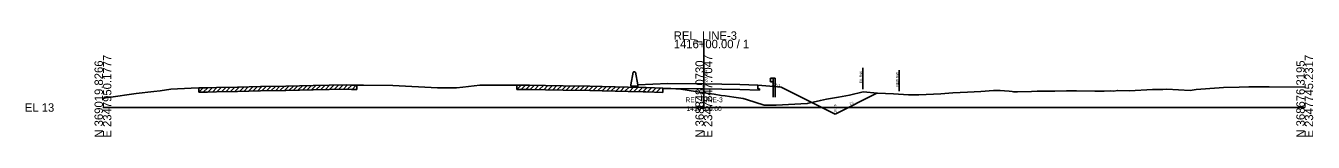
# Model space of a CAD drawing. Extents: x -26 to 2346329, y -10 to 370015.
# Drawn here: x 1974.3 to 2402.8, y 8490.3 to 8525.3 of the extents above; entities that cross this region are included whole.
import ezdxf

# ---------------------------------------------------------------- set-up
doc = ezdxf.new("R2010")
doc.units = 0
for name, color, linetype in [('RD_HC_Cl', 7, 'Continuous'), ('RD_HC_CL_Rel', 7, 'Continuous'), ('RD_HC_Data', 7, 'Continuous'), ('RD_HC_Data_Tic', 7, 'Continuous'), ('RD_HC_Data_Tic_Rel', 7, 'Continuous'), ('RD_HC_TX_Rel_Sta50', 7, 'Continuous'), ('RD_HC_TX_Sta50', 7, 'Continuous'), ('RD_PD_PatLn_526', 7, 'Continuous'), ('RD_PD_PatLn_LINE-A', 7, 'Continuous'), ('RD_PD_PatLn_LINE-B', 7, 'Continuous'), ('RD_PD_PatLn_REL_L-2118', 7, 'Continuous'), ('RD_PD_PatLn_REL_L-2523', 7, 'Continuous'), ('RD_PD_PatLn_Rel_LINE-3', 7, 'Continuous'), ('RD_PD_SuperShp2', 7, 'Continuous'), ('RD_TX_RoadID', 7, 'Continuous'), ('RD_TX_StaOff', 7, 'Continuous'), ('RD_XS_Pave', 7, 'Continuous')]:
    doc.layers.add(name, color=color, linetype=linetype)

msp = doc.modelspace()

# ---------------------------------------------------------------- linework, layer by layer
at = {"layer": 'RD_HC_Cl'}
for p, q in [((2200, 8500), (2200, 8522.45)), ((2000, 8500), (2200, 8500)), ((2200, 8500), (2400, 8500))]:
    msp.add_line(p, q, dxfattribs=at)
at = {"layer": 'RD_HC_Data'}
msp.add_lwpolyline([(2000, 8503.04), (2001.19, 8503.27), (2001.98, 8503.39), (2002.63, 8503.46), (2010.33, 8504.54), (2011.08, 8504.63), (2016.93, 8505.3), (2019.08, 8505.58), (2022.57, 8506.04), (2029.35, 8506.37), (2031.91, 8506.49), (2034.8, 8506.55), (2037.81, 8506.59), (2044.83, 8506.75), (2052.47, 8506.92), (2060.86, 8507.09), (2069.97, 8507.26), (2075.28, 8507.37), (2081.14, 8507.48), (2082.75, 8507.45), (2084.45, 8507.42), (2086.69, 8507.44), (2096.52, 8507.26), (2111.37, 8506.52), (2112.69, 8506.51), (2117.68, 8506.53), (2119.79, 8506.74), (2125.39, 8507.37), (2126.89, 8507.39), (2135.27, 8507.43), (2137.71, 8507.39), (2139.85, 8507.42), (2142, 8507.45), (2147.35, 8507.34), (2153.19, 8507.22), (2162.07, 8507.07), (2166.13, 8507), (2174.86, 8506.8), (2179.77, 8506.68), (2180.66, 8506.65), (2186.39, 8506.44), (2189.03, 8506.29), (2192.38, 8506.08), (2200, 8504.91), (2203.39, 8504.38), (2205.77, 8504.03), (2207.07, 8503.88), (2210, 8503.42), (2213.08, 8503.02), (2214.24, 8502.7), (2220.04, 8500.77), (2224.08, 8500.74), (2234.42, 8501.32), (2238.78, 8502.33), (2240.87, 8502.73), (2244.81, 8503.44), (2248.51, 8504.11), (2253.07, 8505.17), (2257.8, 8504.72), (2263.08, 8504.55), (2268.09, 8504.15), (2271.61, 8504.2), (2278.87, 8504.5), (2282.83, 8504.9), (2287.77, 8505.1), (2292.19, 8505.3), (2296.38, 8505.67), (2298.66, 8505.69), (2300.05, 8505.56), (2301.65, 8505.41), (2302.61, 8505.28), (2303.04, 8505.22), (2303.4, 8505.23), (2304.38, 8505.22), (2309.11, 8505.35), (2311, 8505.41), (2313.93, 8505.41), (2316.79, 8505.38), (2320.68, 8505.57), (2324, 8505.51), (2330.1, 8505.41), (2333.24, 8505.41), (2335.27, 8505.48), (2336.44, 8505.41), (2337.64, 8505.66), (2341.71, 8505.57), (2349.37, 8505.95), (2352.76, 8506), (2354.09, 8506.03), (2361.82, 8505.67), (2363.91, 8505.93), (2371.51, 8506.56), (2373, 8506.59), (2378.21, 8506.73), (2381.4, 8506.82), (2384.57, 8506.9), (2385.38, 8506.88), (2388.17, 8506.86), (2400, 8506.74)], dxfattribs=at)
at = {"layer": 'RD_HC_Data_Tic_Rel'}
for p, q in [((2178, 8507.53), (2178, 8506.73)), ((2225.75, 8506.74), (2243.7, 8497.76)), ((2243.7, 8497.76), (2257.63, 8504.72))]:
    msp.add_line(p, q, dxfattribs=at)
at = {"layer": 'RD_HC_TX_Rel_Sta50'}
for p, q in [((2188, 8507.93), (2200, 8507.84)), ((2200, 8507.84), (2212, 8507.6))]:
    msp.add_line(p, q, dxfattribs=at)
at = {"layer": 'RD_HC_TX_Sta50'}
for p, q in [((2031.91, 8505.05), (2033.38, 8506.52)), ((2031.91, 8505.05), (2031.91, 8506.49)), ((2033.41, 8505.08), (2034.88, 8506.55)), ((2034.91, 8505.11), (2036.37, 8506.57)), ((2036.41, 8505.13), (2037.87, 8506.59)), ((2037.91, 8505.16), (2039.38, 8506.63)), ((2039.41, 8505.19), (2040.88, 8506.66)), ((2040.91, 8505.23), (2042.38, 8506.7)), ((2042.41, 8505.26), (2043.88, 8506.73)), ((2043.91, 8505.29), (2045.38, 8506.76)), ((2045.41, 8505.33), (2046.88, 8506.8)), ((2046.91, 8505.36), (2048.38, 8506.83)), ((2048.41, 8505.4), (2049.88, 8506.87)), ((2049.91, 8505.43), (2051.38, 8506.9)), ((2051.41, 8505.46), (2052.88, 8506.93)), ((2052.91, 8505.5), (2054.38, 8506.96)), ((2054.41, 8505.52), (2055.88, 8506.99)), ((2055.91, 8505.55), (2057.38, 8507.02)), ((2057.41, 8505.58), (2058.88, 8507.05)), ((2058.91, 8505.61), (2060.38, 8507.08)), ((2060.41, 8505.64), (2061.88, 8507.1)), ((2061.91, 8505.67), (2063.38, 8507.13)), ((2063.41, 8505.7), (2064.88, 8507.16)), ((2064.91, 8505.73), (2066.38, 8507.19)), ((2066.41, 8505.75), (2067.88, 8507.22)), ((2067.91, 8505.78), (2069.38, 8507.25)), ((2069.41, 8505.81), (2070.88, 8507.28)), ((2070.91, 8505.84), (2072.38, 8507.31)), ((2072.41, 8505.87), (2073.88, 8507.34)), ((2073.91, 8505.9), (2075.38, 8507.37)), ((2075.41, 8505.93), (2076.88, 8507.4)), ((2076.91, 8505.96), (2078.38, 8507.43)), ((2078.41, 8505.99), (2079.88, 8507.46)), ((2079.91, 8506.02), (2081.37, 8507.48)), ((2081.41, 8506.04), (2082.82, 8507.45)), ((2082.91, 8506.01), (2084.32, 8507.42)), ((2084.45, 8507.42), (2084.45, 8505.98)), ((2137.71, 8505.95), (2139.18, 8507.41)), ((2137.71, 8505.95), (2137.71, 8507.39)), ((2139.21, 8505.98), (2140.67, 8507.43)), ((2140.71, 8506), (2142.16, 8507.44)), ((2142.21, 8506.01), (2143.62, 8507.41)), ((2143.71, 8505.98), (2145.12, 8507.38)), ((2145.21, 8505.95), (2146.62, 8507.35)), ((2146.71, 8505.91), (2148.12, 8507.32)), ((2148.21, 8505.88), (2149.62, 8507.29)), ((2149.71, 8505.85), (2151.12, 8507.26)), ((2151.21, 8505.82), (2152.62, 8507.23)), ((2152.71, 8505.79), (2154.13, 8507.2)), ((2154.21, 8505.76), (2155.63, 8507.18)), ((2155.71, 8505.74), (2157.13, 8507.15)), ((2157.21, 8505.71), (2158.63, 8507.13)), ((2158.71, 8505.69), (2160.13, 8507.1)), ((2160.21, 8505.66), (2161.63, 8507.08)), ((2161.71, 8505.64), (2163.13, 8507.05)), ((2163.21, 8505.61), (2164.63, 8507.03)), ((2164.71, 8505.59), (2166.13, 8507)), ((2166.21, 8505.57), (2167.62, 8506.97)), ((2167.71, 8505.53), (2169.12, 8506.93)), ((2169.21, 8505.49), (2170.62, 8506.9)), ((2170.71, 8505.46), (2172.12, 8506.86)), ((2172.21, 8505.42), (2173.62, 8506.83)), ((2173.71, 8505.39), (2175.12, 8506.79)), ((2175.21, 8505.35), (2176.62, 8506.76)), ((2176.71, 8505.32), (2178.12, 8506.72)), ((2178.21, 8505.28), (2179.62, 8506.69)), ((2179.71, 8505.25), (2181.1, 8506.63)), ((2181.21, 8505.19), (2182.6, 8506.58)), ((2182.71, 8505.13), (2184.1, 8506.52)), ((2184.21, 8505.08), (2185.6, 8506.47)), ((2186.39, 8506.44), (2186.39, 8505)), ((2031.91, 8505.05), (2034.8, 8505.11)), ((2034.8, 8505.11), (2037.81, 8505.15)), ((2037.81, 8505.15), (2044.83, 8505.32)), ((2044.83, 8505.32), (2052.47, 8505.49)), ((2052.47, 8505.49), (2060.86, 8505.65)), ((2060.86, 8505.65), (2069.97, 8505.82)), ((2069.97, 8505.82), (2075.28, 8505.93)), ((2075.28, 8505.93), (2081.14, 8506.04)), ((2081.14, 8506.04), (2082.75, 8506.01)), ((2082.75, 8506.01), (2084.45, 8505.98)), ((2137.71, 8505.95), (2139.85, 8505.99)), ((2139.85, 8505.99), (2142, 8506.01)), ((2142, 8506.01), (2147.35, 8505.9)), ((2147.35, 8505.9), (2153.19, 8505.78)), ((2153.19, 8505.78), (2162.07, 8505.63)), ((2162.07, 8505.63), (2166.13, 8505.57)), ((2166.13, 8505.57), (2174.86, 8505.36)), ((2174.86, 8505.36), (2179.77, 8505.25)), ((2179.77, 8505.25), (2180.66, 8505.21)), ((2180.66, 8505.21), (2186.39, 8505))]:
    msp.add_line(p, q, dxfattribs=at)
at = {"layer": 'RD_PD_PatLn_LINE-A'}
for p, q in [((2218, 8507.36), (2222, 8507.04)), ((2222, 8507.04), (2225.75, 8506.74))]:
    msp.add_line(p, q, dxfattribs=at)
at = {"layer": 'RD_PD_PatLn_LINE-B'}
for p, q in [((2178, 8506.73), (2186.39, 8506.44)), ((2186.39, 8506.44), (2186.39, 8506.23)), ((2218, 8507.36), (2218, 8506.22)), ((2186.39, 8506.23), (2188.03, 8506.29)), ((2188.03, 8506.29), (2199.98, 8506.2)), ((2199.98, 8506.2), (2211.97, 8505.96)), ((2218.5, 8505.7), (2211.97, 8505.96)), ((2218, 8506.22), (2218.5, 8506.18)), ((2218.5, 8506.18), (2218.5, 8505.7))]:
    msp.add_line(p, q, dxfattribs=at)
at = {"layer": 'RD_PD_PatLn_REL_L-2118'}
for p, q in [((2178, 8507.53), (2188, 8507.93)), ((2212, 8507.6), (2218, 8507.36))]:
    msp.add_line(p, q, dxfattribs=at)
at = {"layer": 'RD_PD_PatLn_Rel_LINE-3'}
for p, q in [((2176.46, 8511.67), (2175.67, 8507.53)), ((2176.83, 8511.79), (2176.58, 8511.79)), ((2177.09, 8511.79), (2176.83, 8511.79)), ((2178, 8507.53), (2177.21, 8511.67)), ((2175.67, 8507.53), (2175.67, 8507.13)), ((2175.67, 8507.13), (2176.83, 8507.13)), ((2176.83, 8507.13), (2178, 8507.13)), ((2178, 8507.13), (2178, 8507.53))]:
    msp.add_line(p, q, dxfattribs=at)
for centre, major_axis, start_param, end_param in [((2176.58, 8511.66), (0, -0.133), 3.141593, 4.607459), ((2177.09, 8511.66), (0, 0.133), 4.817319, 6.283185)]:
    msp.add_ellipse(centre, major_axis=major_axis, ratio=0.910156, start_param=start_param, end_param=end_param, dxfattribs=at)
at = {"layer": 'RD_PD_SuperShp2'}
msp.add_line((2265, 8505.39), (2265, 8512.39), dxfattribs=at)
at = {"layer": 'RD_TX_StaOff'}
for p, q in [((2222.17, 8509.62), (2222, 8509.42)), ((2222, 8509.42), (2222, 8509.37)), ((2222, 8509.37), (2222.17, 8509.17)), ((2222, 8508.85), (2222.17, 8509.05)), ((2222, 8508.8), (2222, 8508.85)), ((2222.17, 8508.6), (2222, 8508.8)), ((2222.17, 8508.53), (2222.17, 8509.69)), ((2222.17, 8509.69), (2223.08, 8509.69)), ((2222.17, 8508.53), (2223.08, 8508.53)), ((2223.08, 8509.69), (2223.08, 8506.95)), ((2223.08, 8509.69), (2223.75, 8509.69)), ((2223.08, 8503.48), (2223.08, 8506.95)), ((2223.75, 8509.69), (2223.75, 8506.9)), ((2223.75, 8506.9), (2223.75, 8503.48))]:
    msp.add_line(p, q, dxfattribs=at)
at = {"layer": 'RD_XS_Pave'}
msp.add_line((2252.87, 8506.13), (2252.87, 8513.13), dxfattribs=at)

# ---------------------------------------------------------------- texts
at = {"layer": 'RD_HC_Cl'}
for s, p in [('REL_LINE-3', (2190, 8522.45)), ('1416+00.00 / 1', (2190, 8519.65)), ('EL 13', (1974, 8498.6))]:
    msp.add_text(s, height=2.8, dxfattribs=at).set_placement(p)
for s, p in [('N 369019.8266', (2000, 8490)), ('E 2347950.1777', (2002.8, 8490)), ('N 368848.0730', (2200, 8490)), ('E 2347847.7047', (2202.8, 8490)), ('N 368676.3195', (2400, 8490)), ('E 2347745.2317', (2402.8, 8490))]:
    msp.add_text(s, height=2.8, rotation=90, dxfattribs=at).set_placement(p)
at = {"layer": 'RD_HC_CL_Rel'}
for s, rotation, p in [('12.5:1', 355.4261, (2222.58, 8507.24)), ('2:1', 26.5651, (2248.76, 8500.83))]:
    msp.add_text(s, height=0.75, rotation=rotation, dxfattribs=at).set_placement(p)
at = {"layer": 'RD_HC_Data_Tic'}
msp.add_text('17.91', height=1, rotation=90, dxfattribs=at).set_placement((2200.5, 8504.91))
at = {"layer": 'RD_PD_PatLn_526'}
for s, p in [('REL_LINE-3', (2193.9, 8501.74)), ('1416+00.00', (2194.23, 8498.84))]:
    msp.add_text(s, height=1.6, dxfattribs=at).set_placement(p)
at = {"layer": 'RD_PD_PatLn_REL_L-2523'}
msp.add_text('10.76', height=0.8, rotation=90, dxfattribs=at).set_placement((2244.09, 8498.26))
at = {"layer": 'RD_PD_SuperShp2'}
msp.add_text('NEW R/W ', height=0.75, rotation=90, dxfattribs=at).set_placement((2264.75, 8506.98))
at = {"layer": 'RD_TX_RoadID'}
msp.add_text(' 20.84', height=1.2, rotation=90, dxfattribs=at).set_placement((2201.2, 8507.84))
at = {"layer": 'RD_XS_Pave'}
msp.add_text('EX. R/W ', height=0.75, rotation=90, dxfattribs=at).set_placement((2252.62, 8508.08))

doc.saveas('drawing.dxf')
